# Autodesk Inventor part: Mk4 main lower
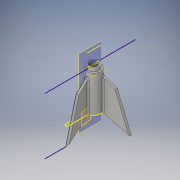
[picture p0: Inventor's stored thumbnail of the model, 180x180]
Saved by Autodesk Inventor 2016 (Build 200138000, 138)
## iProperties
Created: 2015-09
Part Number: Mk4 main lower
Material: Generic
Document SubType Name: Modeling
Designer: lwilliams6899
Density: 1 g/cm^3
Appearance: Default
Author: lwilliams6899
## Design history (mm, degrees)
sketch "Sketch1"
  geometry: C1 r 12.7 at (0, 0); C2 r 10.16 at (0, 0); 1 further point
  constraints: 2 centre point, 2 coincident
  dimensions: "d0" = 25.4 diameter of C1; "d1" = 20.32 diameter of C2
extrude "Extrusion1" new body sketch "Sketch1" distance "d2" = 95.25; taper "d3" = 0 deg
sketch "Sketch2"
  geometry: L1 (0, 0)-(0, 17.288); L2 (0, 17.288)-(1.903, 17.288); L3 (2.54, 12.443)-(2.54, 50.543); L4 (2.54, 50.543)-(-2.54, 50.543); L5 (-2.54, 50.543)-(-2.54, 12.443); C1 r 10.16 at (0, 0) reference; C2 r 15.24 at (0, 0); C3 r 10.16 at (0, 0) reference; A1 r 12.7 centre (0, 0) between (-2.54, 12.443) and (2.54, 12.443) reference; 1 further point
  constraints: 10 end point, 2 perpendicular, 2 point on circle, 1 centre point, 1 coincident, 1 horizontal, 1 vertical
  dimensions: "d4" = 30.48 diameter of C2; "d6" = 38.1 distance of L3.start L3.end; "d7" = 5.08 distance of L3.end L4.end
  node "Projected Loop1"
workplane "Work Plane1"
sketch "Sketch3"
  geometry: L1 (95.25, -29.988)-(95.25, -4.588) reference; L2 (0, -4.588)-(0, -29.988) reference; 1 further point
  node "Projected Loop2"
extrude "Extrusion2" join sketch "Sketch2" distance "d8" = 33.02; taper "d9" = 0 deg; dims "d28" = 58.42, "d29" = 0
sketch "Sketch4"
  geometry: L1 (2.54, 50.543)-(2.54, 12.443) reference; L2 (-2.54, 12.443)-(-2.54, 50.543) reference; L3 (-2.54, 50.543)-(2.54, 50.543) reference; L4 (0, 0)-(2.54, 12.443); L5 (3.353, 16.426)-(4.463, 16.199); C1 r 10.16 at (0, 0) reference; C2 r 12.7 at (0, 0) reference; A1 r 12.7 centre (0, 0) between (2.54, 12.443) and (-2.54, 12.443) reference; 1 further point
  constraints: 4 end point, 1 perpendicular, 1 point on line
  node "Projected Loop3"
  node "Projected Loop4"
workplane "Work Plane2"
workplane "Work Plane3"
sketch "Sketch7"
  geometry: L1 (25.4, -36.83)-(44.193, -55.521); L2 (44.193, -55.521)-(63.243, -128.27); L3 (63.243, -128.27)-(25.143, -95.25); L4 (25.4, -36.83)-(63.243, 1.22); L5 (63.243, 1.22)-(109.24, -28.408); L6 (109.24, -28.408)-(109.24, -130.312); L7 (109.24, -130.312)-(74.411, -170.918); L8 (65.443, -170.918)-(0, -170.918); L9 (0, -170.918)-(-21.879, -137.964); L10 (-21.879, -137.964)-(25.143, -95.25); L11 (12.7, -95.25)-(12.7, -57.623); A1 r 6.887 centre (69.927, -176.146) between (74.411, -170.918) and (65.443, -170.918)
  constraints: 22 end point, 2 point on circle, 2 vertical, 1 centre point, 1 perpendicular, 1 point on line
extrude "Extrusion3" cut sketch "Sketch7" stored distance "d30" = 25.4; taper "d31" = 0 deg
sketch "Sketch8"
  geometry: C1 r 10.16 at (0, 0) reference; C2 r 12.7 at (0, 0) reference; 1 further point
extrude "Extrusion4" cut sketch "Sketch8" distance "d32" = 35.56; taper "d33" = 0 deg
chamfer "Chamfer5" distance "d34" = 2.5146; stored, may be unused: second distance "d35" = 3.175, angle "d36" = 45 deg
fillet "Fillet2" dims "d37" = 3.175
pattern_circular "Circular Pattern2" dims "d39" = 360 deg
sketch "Sketch9" dims "d41" = 17.78
  geometry: L1 (0.025, 14.129)-(0.025, 31.493) reference; L2 (-3.785, 8.044)-(-3.785, 9.429); 3 further points
  constraints: 2 coincident, 2 end point, 6 other
extrude "Extrusion5" join sketch "Sketch9" distance "d46" = 69.85; taper "d47" = 0 deg
sketch "Sketch10"
  geometry: L1 (22.86, -25.4)-(2.54, -25.4) reference; L2 (22.86, -25.4)-(101.995, -25.4); L3 (59.881, -125.356)-(63.243, -128.27) reference; L4 (63.243, -128.27)-(101.995, -128.27); 1 further point
  constraints: 4 end point, 2 horizontal
sketch "Sketch11"
  geometry: 1 further point
workplane "Work Plane6"
sketch "Sketch14"
  geometry: L1 (-8.89, 0.004)-(-8.89, 1.274); L2 (-8.89, 1.274)-(-2.54, 1.274); L3 (-2.54, 1.274)-(-2.54, -1.266); L4 (-2.54, -1.266)-(-8.89, -1.266); L5 (-8.89, -1.266)-(-8.89, 1.274); C1 r 10.16 at (0, 0) reference; A1 r 8.89 centre (0, 0) between (8.89, 0) and (8.89, 0) reference; A2 r 8.89 centre (0, 0) between (8.89, 0) and (8.89, 0) reference; 1 further point
  constraints: 10 end point, 3 perpendicular, 2 point on circle, 1 collinear, 1 point on line, 1 vertical
  dimensions: "d57" = 1.27 distance of L1.start L1.end; "d58" = 6.35 distance of L1.end L2.end; "d59" = 2.54 distance of L2.end L3.end
extrude "Extrusion8" join sketch "Sketch14" stored distance "d60" = 2.159; taper "d61" = 0 deg
fillet "Fillet3" dims "d62" = 0.635
fillet "Fillet4" dims "d63" = 0.635
fillet "Fillet5" dims "d64" = 0.635
thicken "Thicken2" dims "d65" = 0.254, "d66" = 0.254
thicken "Thicken3" dims "d67" = 0.254, "d68" = 0.254
sketch "Sketch15"
  geometry: C1 r 58.191 at (0, 0); A1 r 9.144 centre (0, 0) between (9.144, 0) and (9.144, 0) reference; 1 further point
  constraints: 1 centre point, 1 coincident
extrude "Extrusion9" cut sketch "Sketch15" stored distance "d69" = 0; taper "d70" = 0 deg
sketch "Sketch16"
  geometry: L1 (-1.253, 12.7)-(0, 12.7) reference; C1 r 0.698 at (0, 12.7); C2 r 0.698 at (10.986, -6.372); 2 further points
  constraints: 2 centre point, 2 other
  dimensions: "d71" = 1.397 diameter of C1; "d72" = 1.397 diameter of C2
extrude "Extrusion10" cut sketch "Sketch16" distance "d73" = 25.4; taper "d75" = 0 deg; dims "d74" = 12.7, "d76" = 0
sketch "Sketch17"
  geometry: L1 (0, -112.312)-(0, 48.807) reference; C1 r 10.16 at (0, 0) reference; C2 r 9.144 at (0, 0) reference; C3 r 12.7 at (0, 0) reference; 1 further point
extrude "Extrusion11" join sketch "Sketch17" distance "d77" = 1.27; taper "d78" = 0 deg
sketch "Sketch18"
  geometry: C1 r 12.7 at (0, 0); C2 r 6.985 at (0, 0); 1 further point
  constraints: 2 centre point, 2 coincident
  dimensions: "d79" = 13.97 diameter of C2
extrude "Extrusion12" join sketch "Sketch18" distance "d80" = 5.08; taper "d81" = 0 deg
sketch "Sketch19"
  geometry: C1 r 10.033 at (0, 0); C2 r 7.493 at (0, 0); 1 further point
  constraints: 2 centre point, 2 coincident
  dimensions: "d82" = 20.066 diameter of C1; "d83" = 14.986 diameter of C2
extrude "Extrusion13" join sketch "Sketch19" distance "d84" = 6.35; taper "d85" = 0 deg
sketch "Sketch20"
  geometry: L1 (22.733, -22.86)-(2.667, -22.86) reference; L2 (2.667, -22.86)-(-63.311, -22.86); 1 further point
  constraints: 2 end point, 1 horizontal
body "Solid1"
node "Projected Loop12"
node "Projected Loop14"
node "Projected Loop15"
other parameters: "d10" = 90 deg, "d42" = 3.81, "d43" = 3.81, "d44" = 3.81, "d45" = 3.81, "d56" = -7.62
